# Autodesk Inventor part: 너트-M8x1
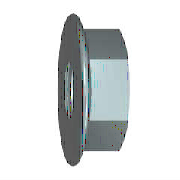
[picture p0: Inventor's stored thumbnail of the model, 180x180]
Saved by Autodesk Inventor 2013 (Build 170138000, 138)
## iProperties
Created: 2015-12
Part Number: 너트-M8x1
Material: 스테인리스강
Description: 플랜지붙이 6각 너트 - 일반 스레드
Document SubType Name: Modeling
Standard: ISO 4161
Designer: mdu
Standard Revision: 2판 1999-03-15
Standards Organization: ISO
Language: ko-KR
Size Designation: M8
Categories: <MemberInstance><Categories><Category DisplayName="조임쇠" InternalName="e4da775c-781d-43d5-af7c-5136215cf5a6" Mnemonic="FSTN"><Category DisplayName="너트" InternalN
Density: 8.08 g/cm^3
Author: mdu
IsCustomPart: 1
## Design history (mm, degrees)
sketch "스케치1"
  geometry: L1 (-1.844, 0)-(9.641, 0) reference; L2 (3.107, 6.5)-(2.288, 8.257); L3 (3.107, 6.5)-(8, 6.5); L4 (8, 6.5)-(8, 0); L5 (3.107, 6.5)-(3.107, 0); L6 (0, -1.835)-(0, 11.01) reference; A1 r 1.2 centre (1.2, 7.75) between (2.288, 8.257) and (0, 7.75); 1 further point
  constraints: 8 end point, 3 point on line, 2 perpendicular, 2 point on circle, 2 tangent, 1 centre point, 1 parallel
  dimensions: "d2" = 13 diameter of L3 L1 (= SW); "d4" = 17.9 dimension on A1 L1 (= LADI); "d5" = 1.2 radius of A1 (= PHH); "d15" = 8 distance between parallel lines of L4 L6 (= KOH); "d16" = 25 deg angle of L6 L2 (= KEWI)
revolve "링" sketch "스케치1" stored, may be unused: angle "d8" = 90 deg
sketch "스케치2"
  geometry: L1 (-6.5, -3.753)-(-6.5, 3.753); L2 (-6.5, 3.753)-(0, 7.506); L3 (0, 7.506)-(6.5, 3.753); L4 (6.5, 3.753)-(6.5, -3.753); L5 (6.5, -3.753)-(0, -7.506); L6 (0, -7.506)-(-6.5, -3.753); C1 r 4.9 at (0, 0); C2 r 7.75 at (0, 0) reference; 1 further point
  constraints: 12 end point, 1 centre point, 1 coincident, 1 vertical, 11 other
  dimensions: "d6" = 15.01111 distance of L5.end L2.end (= 1.1547 x SW)
extrude "본체" join sketch "스케치2" distance "d7" = 8 (= KOH); taper "d9" = 0 deg
sketch "스케치3"
  geometry: L1 (2.638, 7.506)-(8, 7.506) reference; L2 (8, 3.753)-(8, 7.506) reference; L3 (0, -7.75)-(0, 7.75) reference; L4 (-1.6, 0)-(9.6, 0) reference; L5 (7.419, 7.506)-(8, 6.5)
  constraints: 2 end point, 2 point on line
  dimensions: "d10" = 30 deg angle of L2 L5 (= ANG1); "d11" = 13 diameter of L5.end L4 (= SW0)
revolve "모따기1" sketch "스케치3" stored, may be unused: angle "d24" = 90 deg
sketch "스케치4"
  geometry: C1 r 7.75 at (0, 0) reference; 1 further point
  constraints: 1 coincident
hole "스레드" sketch "스케치4" at (0, 0) diameter "d25" = 6.647; stored, may be unused: countersink angle "d29" = 82 deg, drill point angle "d31" = 118 deg; dims "d26" = 6, "d27" = 4, "d28" = 2, "d30" = 8
workaxis "Work Axis1"
workplane "Work Plane1"
body "Solid1"
chamfer "모따기2" distance "d12" = 0.67658 (= -0.5 x GD1 + 0.5 x NND); stored, may be unused: angle "d13" = 30 deg, second distance "d46" = 0.67658 (= -0.5 x GD1 + 0.5 x NND)
chamfer "모따기3" distance "d51" = 0.67658 (= -0.5 x GD1 + 0.5 x NND); stored, may be unused: second distance "d52" = 2, angle "d53" = 45 deg
other parameters: "ANG1" = 30 deg [user parameter; used in 1 equation term], "KEWI" = 25 deg [user parameter; used in 1 equation term], "NND" = 8 [user parameter; used in 4 equation terms], "LADI" = 17.9 [user parameter; used in 2 equation terms], "SW" = 13 [user parameter; used in 3 equation terms], "PHH" = 1.2 [user parameter; used in 3 equation terms], "KOH" = 8 (= NND) [user parameter; used in 2 equation terms], "SW0" = 13 [user parameter; used in 1 equation term], "GD1" = 6.64684 (computed from THREADDIA, PTC, TOA) [user parameter; used in 3 equation terms], "d1" = 17.9 (= LADI), "d3" = 1.2 (= PHH), "d45" = 0, "d47" = 0, "d49" = 0, "d54" = 0, "GUL" = 0.67658 (= 0.541266 x PTC) [user parameter], "TPU" = 8 (computed from PTC) [user parameter], "RR" = 1.2 (= PHH) [user parameter], "THREADDIA" = 8 [user parameter; used in 1 equation term], "TOA" = 30 deg [user parameter; used in 1 equation term], "PTC" = 1.25 [user parameter; used in 4 equation terms], "GAL" = 0.67658 (= 0.541266 x PTC) [user parameter], "E0" = 15.015 (= 1.155 x SW) [user parameter]
